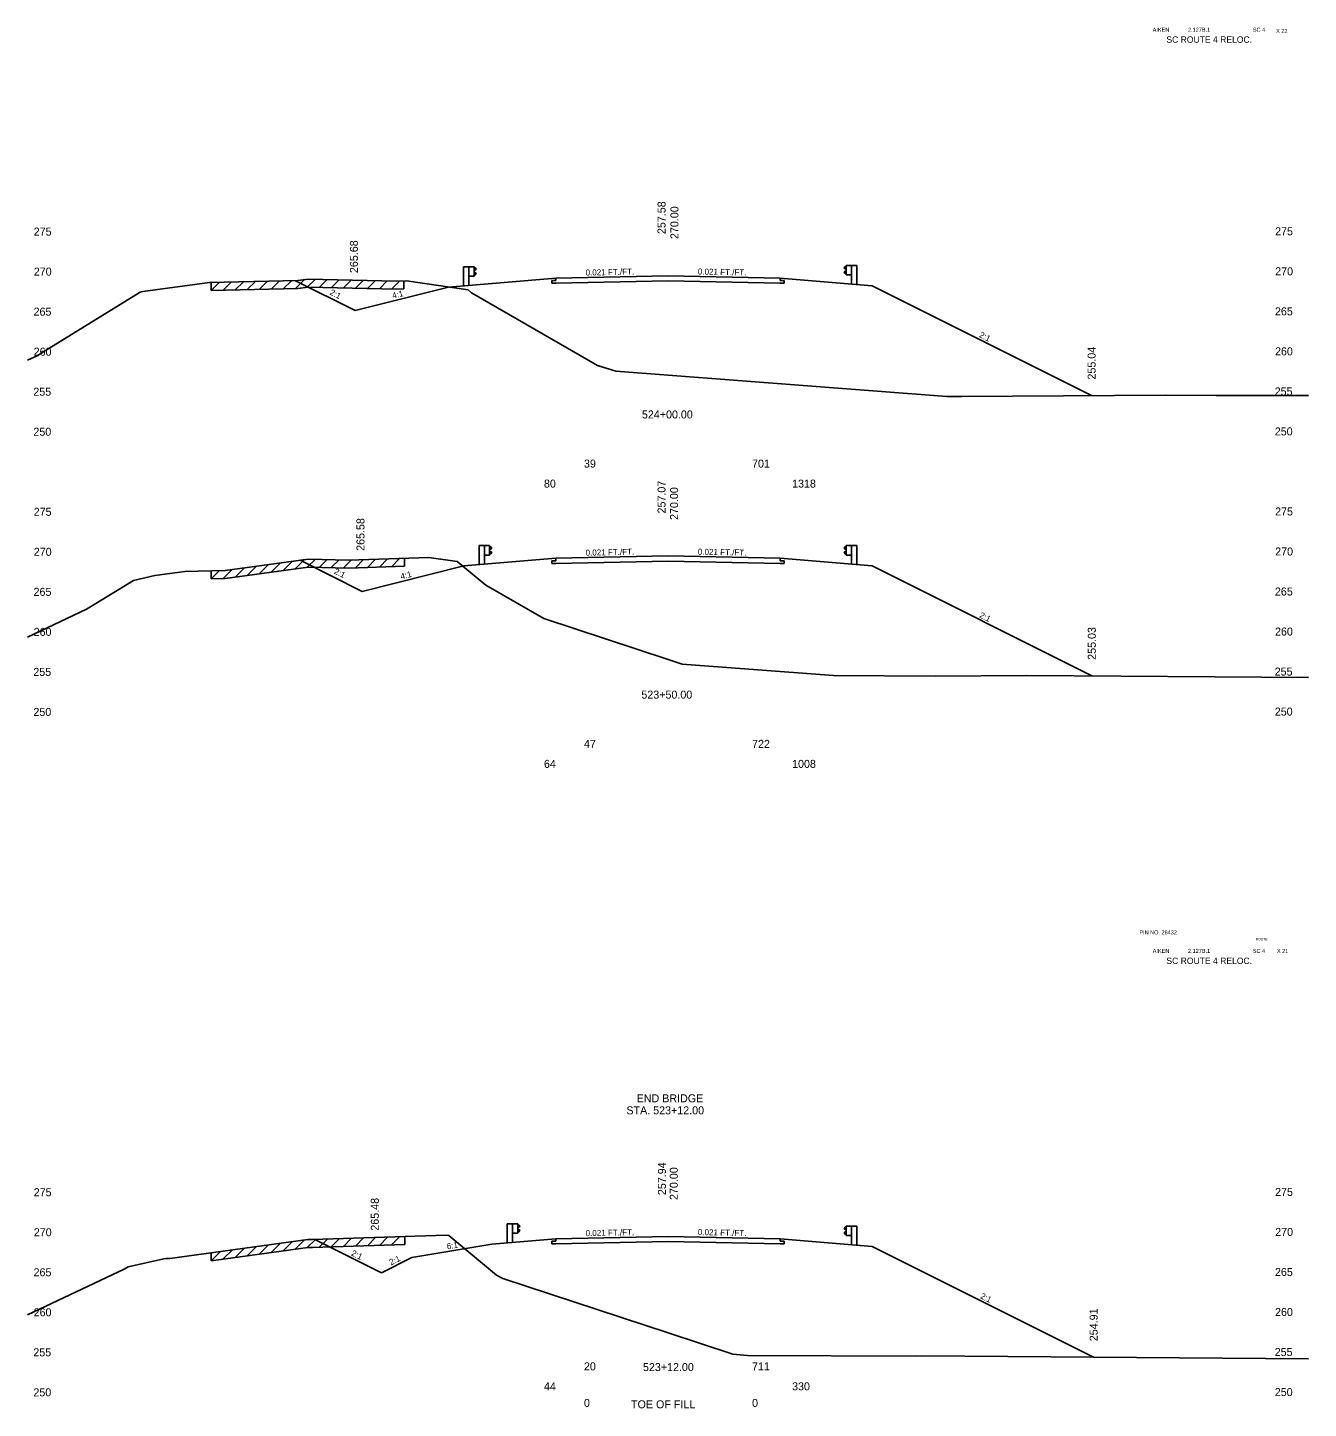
# Model space of a CAD drawing. Extents: x 2967 to 4323, y -3677 to -817.
# Drawn here: x 3188.8 to 3348.8, y -1336.3 to -1163.8 of the extents above; entities that cross this region are included whole.
import ezdxf

# ---------------------------------------------------------------- set-up
doc = ezdxf.new("R2010")
doc.units = 0
for name, color, linetype in [('Level 1', 7, 'Continuous'), ('Level 10', 7, 'Continuous'), ('Level 11', 7, 'Continuous'), ('Level 12', 7, 'Continuous'), ('Level 20', 7, 'Continuous'), ('Level 24', 7, 'Continuous'), ('Level 3', 7, 'Continuous'), ('Level 32', 7, 'Continuous'), ('Level 33', 7, 'Continuous'), ('Level 59', 7, 'Continuous'), ('Level 6', 7, 'Continuous'), ('Level 60', 7, 'Continuous'), ('Level 61', 7, 'Continuous'), ('Level 7', 7, 'Continuous')]:
    doc.layers.add(name, color=color, linetype=linetype)

msp = doc.modelspace()

# ---------------------------------------------------------------- linework, layer by layer
at = {"layer": 'Level 11'}
for p, q in [((3254.76, -1195.13), (3254.76, -1195.43)), ((3282.76, -1195.43), (3282.76, -1195.13)), ((3254.76, -1195.43), (3254.26, -1195.44)), ((3254.26, -1195.44), (3254.26, -1195.78)), ((3254.26, -1195.78), (3254.76, -1195.77)), ((3283.26, -1195.44), (3282.76, -1195.43)), ((3282.76, -1195.77), (3283.26, -1195.78)), ((3283.26, -1195.78), (3283.26, -1195.44)), ((3254.76, -1230.43), (3254.26, -1230.44)), ((3254.26, -1230.44), (3254.26, -1230.78)), ((3254.26, -1230.78), (3254.76, -1230.77)), ((3254.76, -1230.13), (3254.76, -1230.43)), ((3282.76, -1230.43), (3282.76, -1230.13)), ((3283.26, -1230.44), (3282.76, -1230.43)), ((3282.76, -1230.77), (3283.26, -1230.78)), ((3283.26, -1230.78), (3283.26, -1230.44)), ((3254.76, -1315.43), (3254.26, -1315.44)), ((3254.76, -1315.43), (3254.26, -1315.44)), ((3254.26, -1315.44), (3254.26, -1315.78)), ((3254.26, -1315.44), (3254.26, -1315.78)), ((3254.26, -1315.78), (3254.76, -1315.77)), ((3254.26, -1315.78), (3254.76, -1315.77)), ((3254.76, -1315.13), (3254.76, -1315.43)), ((3254.76, -1315.13), (3254.76, -1315.43)), ((3282.76, -1315.43), (3282.76, -1315.13)), ((3282.76, -1315.43), (3282.76, -1315.13)), ((3283.26, -1315.44), (3282.76, -1315.43)), ((3283.26, -1315.44), (3282.76, -1315.43)), ((3282.76, -1315.77), (3283.26, -1315.78)), ((3282.76, -1315.77), (3283.26, -1315.78)), ((3283.26, -1315.78), (3283.26, -1315.44)), ((3283.26, -1315.78), (3283.26, -1315.44))]:
    msp.add_line(p, q, dxfattribs=at)
at = {"layer": 'Level 12'}
for p, q in [((3268.76, -1195.48), (3254.76, -1195.77)), ((3282.76, -1195.77), (3268.76, -1195.48)), ((3268.76, -1230.48), (3254.76, -1230.77)), ((3282.76, -1230.77), (3268.76, -1230.48)), ((3291.03, -1313.62), (3290.76, -1313.82)), ((3290.76, -1313.82), (3290.76, -1313.87)), ((3290.76, -1313.87), (3291.03, -1314.07)), ((3290.76, -1314.39), (3291.03, -1314.19)), ((3291.03, -1314.72), (3291.03, -1313.55)), ((3291.03, -1313.55), (3291.7, -1313.55)), ((3291.7, -1313.55), (3291.7, -1315.88)), ((3291.7, -1313.55), (3292.36, -1313.55)), ((3292.36, -1313.55), (3292.36, -1315.93)), ((3246.76, -1315.8), (3254.76, -1315.13)), ((3254.76, -1315.43), (3254.26, -1315.44)), ((3254.26, -1315.44), (3254.26, -1315.78)), ((3254.26, -1315.78), (3254.76, -1315.77)), ((3254.76, -1315.13), (3268.76, -1314.84)), ((3254.76, -1315.13), (3268.76, -1314.84)), ((3254.76, -1315.13), (3268.76, -1314.84)), ((3254.76, -1315.13), (3254.76, -1315.43)), ((3268.76, -1315.48), (3254.76, -1315.77)), ((3268.76, -1315.48), (3254.76, -1315.77)), ((3268.76, -1315.48), (3254.76, -1315.77)), ((3268.76, -1314.84), (3282.76, -1315.13)), ((3268.76, -1314.84), (3282.76, -1315.13)), ((3268.76, -1314.84), (3282.76, -1315.13)), ((3282.76, -1315.77), (3268.76, -1315.48)), ((3282.76, -1315.77), (3268.76, -1315.48)), ((3282.76, -1315.77), (3268.76, -1315.48)), ((3282.76, -1315.13), (3290.76, -1315.8)), ((3282.76, -1315.43), (3282.76, -1315.13)), ((3283.26, -1315.44), (3282.76, -1315.43)), ((3282.76, -1315.77), (3283.26, -1315.78)), ((3283.26, -1315.78), (3283.26, -1315.44)), ((3290.76, -1314.44), (3290.76, -1314.39)), ((3291.03, -1314.64), (3290.76, -1314.44)), ((3290.76, -1315.8), (3294.26, -1316.09)), ((3291.03, -1314.72), (3291.7, -1314.72)), ((3294.26, -1316.09), (3321.93, -1329.93))]:
    msp.add_line(p, q, dxfattribs=at)
at = {"layer": 'Level 24'}
for p, q in [((3291.03, -1194.72), (3291.03, -1193.55)), ((3291.03, -1193.55), (3291.7, -1193.55)), ((3291.7, -1193.55), (3291.7, -1195.88)), ((3291.7, -1193.55), (3292.36, -1193.55)), ((3292.36, -1193.55), (3292.36, -1195.93)), ((3243.21, -1193.71), (3243.21, -1196.1)), ((3243.21, -1193.71), (3243.88, -1193.71)), ((3244.54, -1193.71), (3243.88, -1193.71)), ((3243.88, -1193.71), (3243.88, -1196.04)), ((3244.54, -1194.88), (3243.88, -1194.88)), ((3244.54, -1194.88), (3244.54, -1193.71)), ((3244.54, -1193.78), (3244.81, -1193.98)), ((3244.81, -1194.03), (3244.54, -1194.23)), ((3244.81, -1194.56), (3244.54, -1194.36)), ((3244.54, -1194.81), (3244.81, -1194.61)), ((3244.81, -1193.98), (3244.81, -1194.03)), ((3244.81, -1194.61), (3244.81, -1194.56)), ((3291.03, -1193.62), (3290.76, -1193.82)), ((3290.76, -1193.82), (3290.76, -1193.87)), ((3290.76, -1193.87), (3291.03, -1194.07)), ((3290.76, -1194.39), (3291.03, -1194.19)), ((3290.76, -1194.44), (3290.76, -1194.39)), ((3291.03, -1194.64), (3290.76, -1194.44)), ((3291.03, -1194.72), (3291.7, -1194.72)), ((3245.15, -1228.55), (3245.15, -1230.93)), ((3245.15, -1228.55), (3245.82, -1228.55)), ((3246.48, -1228.55), (3245.82, -1228.55)), ((3245.82, -1228.55), (3245.82, -1230.88)), ((3246.48, -1229.72), (3245.82, -1229.72)), ((3246.48, -1229.72), (3246.48, -1228.55)), ((3246.48, -1228.62), (3246.76, -1228.82)), ((3246.76, -1228.87), (3246.48, -1229.07)), ((3246.76, -1229.39), (3246.48, -1229.19)), ((3246.48, -1229.64), (3246.76, -1229.44)), ((3246.76, -1228.82), (3246.76, -1228.87)), ((3246.76, -1229.44), (3246.76, -1229.39)), ((3291.03, -1228.62), (3290.76, -1228.82)), ((3290.76, -1228.82), (3290.76, -1228.87)), ((3290.76, -1228.87), (3291.03, -1229.07)), ((3290.76, -1229.39), (3291.03, -1229.19)), ((3290.76, -1229.44), (3290.76, -1229.39)), ((3291.03, -1229.64), (3290.76, -1229.44)), ((3291.03, -1229.72), (3291.03, -1228.55)), ((3291.03, -1228.55), (3291.7, -1228.55)), ((3291.03, -1229.72), (3291.7, -1229.72)), ((3291.7, -1228.55), (3291.7, -1230.88)), ((3291.7, -1228.55), (3292.36, -1228.55)), ((3292.36, -1228.55), (3292.36, -1230.93)), ((3248.66, -1313.26), (3248.66, -1315.64)), ((3248.66, -1313.26), (3249.32, -1313.26)), ((3249.99, -1313.26), (3249.32, -1313.26)), ((3249.32, -1313.26), (3249.32, -1315.59)), ((3249.99, -1314.42), (3249.99, -1313.26)), ((3249.99, -1313.33), (3250.26, -1313.53)), ((3250.26, -1313.58), (3249.99, -1313.78)), ((3250.26, -1314.1), (3249.99, -1313.9)), ((3249.99, -1314.35), (3250.26, -1314.15)), ((3250.26, -1313.53), (3250.26, -1313.58)), ((3250.26, -1314.15), (3250.26, -1314.1)), ((3291.03, -1313.62), (3290.76, -1313.82)), ((3291.03, -1313.62), (3290.76, -1313.82)), ((3290.76, -1313.82), (3290.76, -1313.87)), ((3290.76, -1313.82), (3290.76, -1313.87)), ((3290.76, -1313.87), (3291.03, -1314.07)), ((3290.76, -1313.87), (3291.03, -1314.07)), ((3290.76, -1314.39), (3291.03, -1314.19)), ((3290.76, -1314.39), (3291.03, -1314.19)), ((3291.03, -1314.72), (3291.03, -1313.55)), ((3291.03, -1313.55), (3291.7, -1313.55)), ((3291.03, -1314.72), (3291.03, -1313.55)), ((3291.03, -1313.55), (3291.7, -1313.55)), ((3291.7, -1313.55), (3291.7, -1315.88)), ((3291.7, -1313.55), (3292.36, -1313.55)), ((3291.7, -1313.55), (3291.7, -1315.88)), ((3291.7, -1313.55), (3292.36, -1313.55)), ((3292.36, -1313.55), (3292.36, -1315.93)), ((3292.36, -1313.55), (3292.36, -1315.93)), ((3249.99, -1314.42), (3249.32, -1314.42)), ((3290.76, -1314.44), (3290.76, -1314.39)), ((3290.76, -1314.44), (3290.76, -1314.39)), ((3291.03, -1314.64), (3290.76, -1314.44)), ((3291.03, -1314.64), (3290.76, -1314.44)), ((3291.03, -1314.72), (3291.7, -1314.72)), ((3291.03, -1314.72), (3291.7, -1314.72))]:
    msp.add_line(p, q, dxfattribs=at)
at = {"layer": 'Level 59'}
for p, q in [((3254.76, -1195.13), (3268.76, -1194.84)), ((3268.76, -1194.84), (3282.76, -1195.13)), ((3254.76, -1230.13), (3268.76, -1229.84)), ((3268.76, -1229.84), (3282.76, -1230.13)), ((3254.76, -1315.13), (3268.76, -1314.84)), ((3254.76, -1315.13), (3268.76, -1314.84)), ((3268.76, -1314.84), (3282.76, -1315.13)), ((3268.76, -1314.84), (3282.76, -1315.13))]:
    msp.add_line(p, q, dxfattribs=at)
at = {"layer": 'Level 6'}
for p, q in [((3241.32, -1196.25), (3254.76, -1195.13)), ((3282.76, -1195.13), (3290.76, -1195.8)), ((3241.32, -1196.25), (3229.67, -1199.17)), ((3290.76, -1195.8), (3294.26, -1196.09)), ((3243.26, -1231.09), (3230.57, -1234.26)), ((3243.26, -1231.09), (3254.76, -1230.13)), ((3282.76, -1230.13), (3290.76, -1230.8)), ((3290.76, -1230.8), (3294.26, -1231.09)), ((3246.76, -1315.8), (3254.76, -1315.13)), ((3246.76, -1315.8), (3254.76, -1315.13)), ((3282.76, -1315.13), (3290.76, -1315.8)), ((3282.76, -1315.13), (3290.76, -1315.8)), ((3290.76, -1315.8), (3294.26, -1316.09)), ((3290.76, -1315.8), (3294.26, -1316.09))]:
    msp.add_line(p, q, dxfattribs=at)
at = {"layer": 'Level 60'}
for p, q in [((3222.52, -1195.44), (3223.81, -1195.27)), ((3223.81, -1195.27), (3234.84, -1195.51)), ((3190.86, -1204.27), (3202.82, -1196.9)), ((3202.82, -1196.9), (3203.17, -1196.82)), ((3203.17, -1196.82), (3211.46, -1195.66)), ((3211.46, -1195.66), (3222.52, -1195.44)), ((3234.84, -1195.51), (3236.08, -1195.47)), ((3236.08, -1195.47), (3243.78, -1196.58)), ((3243.78, -1196.58), (3244.23, -1196.95)), ((3244.23, -1196.95), (3259.96, -1206.03)), ((3188.76, -1205.38), (3189.94, -1204.82)), ((3189.94, -1204.82), (3190.86, -1204.27)), ((3259.96, -1206.03), (3262.23, -1206.77)), ((3262.23, -1206.77), (3268.76, -1207.27)), ((3268.76, -1207.27), (3303.6, -1209.91)), ((3303.6, -1209.91), (3305.42, -1209.92)), ((3305.42, -1209.92), (3330.89, -1209.74)), ((3330.89, -1209.74), (3337.23, -1209.78)), ((3337.23, -1209.78), (3348.76, -1209.78)), ((3213.43, -1231.66), (3223.79, -1230.24)), ((3223.79, -1230.24), (3228.89, -1230.35)), ((3228.89, -1230.35), (3238.89, -1230.03)), ((3238.89, -1230.03), (3242.42, -1230.54)), ((3242.42, -1230.54), (3245.99, -1233.49)), ((3196.53, -1236.25), (3201.98, -1232.89)), ((3201.98, -1232.89), (3204.64, -1232.28)), ((3204.64, -1232.28), (3208.41, -1231.76)), ((3208.41, -1231.76), (3213.43, -1231.66)), ((3245.99, -1233.49), (3253.23, -1237.67)), ((3188.76, -1239.97), (3196.11, -1236.5)), ((3196.11, -1236.5), (3196.53, -1236.25)), ((3253.23, -1237.67), (3268.76, -1242.77)), ((3268.76, -1242.77), (3270.54, -1243.36)), ((3270.54, -1243.36), (3289.44, -1244.79)), ((3289.44, -1244.79), (3302.12, -1244.84)), ((3302.12, -1244.84), (3313.6, -1244.76)), ((3313.6, -1244.76), (3348.76, -1245.01)), ((3206.51, -1317.58), (3223.77, -1315.21)), ((3223.77, -1315.21), (3224.36, -1315.23)), ((3224.36, -1315.23), (3241.03, -1314.69)), ((3241.03, -1314.69), (3241.39, -1314.74)), ((3241.39, -1314.74), (3247.33, -1319.66)), ((3201.34, -1318.65), (3205.76, -1317.63)), ((3205.76, -1317.63), (3206.08, -1317.58)), ((3206.08, -1317.58), (3206.51, -1317.58)), ((3188.76, -1324.65), (3200.84, -1318.95)), ((3200.84, -1318.95), (3201.34, -1318.65)), ((3247.33, -1319.66), (3248.12, -1320.11)), ((3248.12, -1320.11), (3268.76, -1326.9)), ((3268.76, -1326.9), (3276.85, -1329.56)), ((3276.85, -1329.56), (3278.68, -1329.7)), ((3278.68, -1329.7), (3299.62, -1329.78)), ((3299.62, -1329.78), (3300.46, -1329.77)), ((3300.46, -1329.77), (3348.76, -1330.12))]:
    msp.add_line(p, q, dxfattribs=at)
at = {"layer": 'Level 61'}
for p, q in [((3224.7, -1195.29), (3223.7, -1196.28)), ((3212.72, -1195.64), (3211.7, -1196.66)), ((3211.7, -1195.66), (3211.7, -1196.66)), ((3211.7, -1196.66), (3222.52, -1196.44)), ((3214.22, -1195.61), (3213.2, -1196.63)), ((3215.72, -1195.58), (3214.7, -1196.6)), ((3217.22, -1195.55), (3216.2, -1196.57)), ((3218.72, -1195.52), (3217.7, -1196.54)), ((3220.22, -1195.49), (3219.2, -1196.51)), ((3221.72, -1195.46), (3220.7, -1196.48)), ((3223.32, -1195.34), (3222.2, -1196.45)), ((3222.52, -1196.44), (3223.81, -1196.27)), ((3223.81, -1196.27), (3234.84, -1196.51)), ((3226.18, -1195.32), (3225.2, -1196.3)), ((3227.68, -1195.35), (3226.7, -1196.33)), ((3229.18, -1195.39), (3228.2, -1196.36)), ((3230.68, -1195.42), (3229.7, -1196.4)), ((3232.18, -1195.45), (3231.2, -1196.43)), ((3233.68, -1195.48), (3232.7, -1196.46)), ((3235.2, -1195.5), (3234.2, -1196.5)), ((3234.84, -1196.51), (3235.77, -1196.48)), ((3235.77, -1196.48), (3235.77, -1195.48)), ((3213.43, -1232.66), (3223.79, -1231.24)), ((3215.86, -1231.32), (3214.7, -1232.48)), ((3217.36, -1231.12), (3216.2, -1232.28)), ((3218.86, -1230.91), (3217.7, -1232.07)), ((3220.36, -1230.71), (3219.2, -1231.87)), ((3221.86, -1230.5), (3220.7, -1231.66)), ((3223.36, -1230.3), (3222.2, -1231.46)), ((3224.69, -1230.26), (3223.7, -1231.25)), ((3223.79, -1231.24), (3228.89, -1231.35)), ((3226.18, -1230.29), (3225.2, -1231.27)), ((3227.68, -1230.32), (3226.7, -1231.3)), ((3229.2, -1230.34), (3228.2, -1231.33)), ((3228.89, -1231.35), (3235.83, -1231.13)), ((3230.73, -1230.29), (3229.7, -1231.32)), ((3232.23, -1230.24), (3231.2, -1231.27)), ((3233.73, -1230.19), (3232.7, -1231.23)), ((3235.23, -1230.14), (3234.2, -1231.18)), ((3235.83, -1231.13), (3235.83, -1230.13)), ((3212.72, -1231.67), (3211.7, -1232.69)), ((3211.7, -1231.69), (3211.7, -1232.69)), ((3211.7, -1232.69), (3213.43, -1232.66)), ((3214.33, -1231.53), (3213.2, -1232.66)), ((3218.86, -1315.89), (3217.7, -1317.05)), ((3220.36, -1315.68), (3219.2, -1316.84)), ((3221.86, -1315.48), (3220.7, -1316.64)), ((3223.36, -1315.27), (3222.2, -1316.43)), ((3224.71, -1315.22), (3223.7, -1316.23)), ((3224.36, -1316.23), (3235.88, -1315.86)), ((3226.23, -1315.17), (3225.2, -1316.2)), ((3227.73, -1315.12), (3226.7, -1316.15)), ((3229.23, -1315.07), (3228.2, -1316.1)), ((3230.73, -1315.02), (3229.7, -1316.06)), ((3232.23, -1314.97), (3231.2, -1316.01)), ((3233.73, -1314.93), (3232.7, -1315.96)), ((3235.23, -1314.88), (3234.2, -1315.91)), ((3235.88, -1315.86), (3235.88, -1314.86)), ((3211.7, -1317.87), (3223.77, -1316.21)), ((3212.86, -1316.71), (3211.7, -1317.87)), ((3211.7, -1316.87), (3211.7, -1317.87)), ((3214.36, -1316.5), (3213.2, -1317.66)), ((3215.86, -1316.3), (3214.7, -1317.46)), ((3217.36, -1316.09), (3216.2, -1317.25)), ((3223.77, -1316.21), (3224.36, -1316.23))]:
    msp.add_line(p, q, dxfattribs=at)
at = {"layer": 'Level 7'}
for p, q in [((3222.23, -1195.45), (3229.67, -1199.17)), ((3294.26, -1196.09), (3321.68, -1209.8)), ((3222.79, -1230.37), (3230.57, -1234.26)), ((3294.26, -1231.09), (3321.7, -1244.81)), ((3224.66, -1315.22), (3232.96, -1319.37)), ((3236.76, -1317.47), (3246.76, -1315.8)), ((3236.76, -1317.47), (3232.96, -1319.37)), ((3294.26, -1316.09), (3321.93, -1329.93)), ((3294.26, -1316.09), (3321.93, -1329.93))]:
    msp.add_line(p, q, dxfattribs=at)

# ---------------------------------------------------------------- texts
at = {"layer": 'Level 1'}
for s, p in [('39', (3258.26, -1218.8)), ('701', (3279.26, -1218.8)), ('80', (3253.26, -1221.3)), ('1318', (3284.26, -1221.3)), ('47', (3258.26, -1253.81)), ('722', (3279.26, -1253.81)), ('64', (3253.26, -1256.31)), ('1008', (3284.26, -1256.31)), ('STA. 523+12.00', (3263.56, -1299.59)), ('END BRIDGE', (3264.84, -1298.09)), ('20', (3258.26, -1331.57)), ('711', (3279.26, -1331.57)), ('44', (3253.26, -1334.07)), ('330', (3284.26, -1334.07)), ('0', (3258.26, -1336.14)), ('0', (3279.26, -1336.14))]:
    msp.add_text(s, height=1, dxfattribs=at).set_placement(p)
at = {"layer": 'Level 10'}
for s, p in [('257.58', (3268.45, -1189.63)), ('257.07', (3268.45, -1224.53)), ('257.94', (3268.5, -1309.68))]:
    msp.add_text(s, height=1, rotation=90, dxfattribs=at).set_placement(p)
for s, p in [('524+00.00', (3265.5, -1212.66)), ('523+50.00', (3265.43, -1247.66)), ('523+12.00', (3265.63, -1331.66)), ('TOE OF FILL', (3264.14, -1336.31))]:
    msp.add_text(s, height=1, dxfattribs=at).set_placement(p)
at = {"layer": 'Level 20'}
for s, height, p in [('AIKEN', 0.5, (3329.31, -1164.35)), (' 2.127B.1', 0.5, (3333.53, -1164.35)), ('SC 4', 0.5, (3341.82, -1164.35)), ('X 22', 0.5, (3344.73, -1164.51)), ('SC ROUTE 4 RELOC.', 0.8, (3331.02, -1165.73)), ('PIN NO. 26432', 0.5, (3327.65, -1277.11)), ('ROUTE', 0.3, (3342.19, -1277.85)), ('AIKEN', 0.5, (3329.31, -1279.42)), (' 2.127B.1', 0.5, (3333.53, -1279.42)), ('SC 4', 0.5, (3341.82, -1279.42)), ('X 21', 0.5, (3344.83, -1279.43)), ('SC ROUTE 4 RELOC.', 0.8, (3331.02, -1280.81))]:
    msp.add_text(s, height=height, dxfattribs=at).set_placement(p)
at = {"layer": 'Level 3'}
for s, p in [(' 275', (3189.15, -1189.82)), (' 275', (3344.23, -1189.78)), (' 270', (3189.16, -1194.82)), (' 270', (3344.24, -1194.78)), (' 265', (3189.13, -1199.82)), (' 265', (3344.21, -1199.78)), (' 260', (3189.14, -1204.82)), (' 260', (3344.22, -1204.78)), (' 255', (3189.1, -1209.82)), (' 255', (3344.18, -1209.78)), (' 250', (3189.11, -1214.82)), (' 250', (3344.19, -1214.78)), (' 275', (3189.15, -1224.82)), (' 275', (3344.23, -1224.78)), (' 270', (3189.16, -1229.82)), (' 270', (3344.24, -1229.78)), (' 265', (3189.13, -1234.82)), (' 265', (3344.21, -1234.78)), (' 260', (3189.14, -1239.82)), (' 260', (3344.22, -1239.78)), (' 255', (3189.1, -1244.82)), (' 255', (3344.18, -1244.78)), (' 250', (3344.19, -1249.78)), (' 250', (3189.11, -1249.82)), (' 275', (3189.15, -1309.82)), (' 275', (3344.23, -1309.78)), (' 270', (3189.16, -1314.82)), (' 270', (3344.24, -1314.78)), (' 265', (3189.13, -1319.82)), (' 265', (3344.21, -1319.78)), (' 260', (3189.14, -1324.82)), (' 260', (3344.22, -1324.78)), (' 255', (3189.1, -1329.82)), (' 255', (3344.18, -1329.78)), (' 250', (3189.11, -1334.82)), (' 250', (3344.19, -1334.78))]:
    msp.add_text(s, height=1, dxfattribs=at).set_placement(p)
at = {"layer": 'Level 32'}
for s, rotation, p in [('0.021 FT./FT.', 1.1916, (3258.47, -1194.81)), ('0.021 FT./FT.', 358.8084, (3272.48, -1194.67)), ('2:1', 333.435, (3226.43, -1197.15)), ('4:1', 14.0362, (3234.4, -1197.71)), ('2:1', 333.435, (3307.57, -1202.47)), ('0.021 FT./FT.', 1.1916, (3258.47, -1229.81)), ('0.021 FT./FT.', 358.8084, (3272.48, -1229.67)), ('2:1', 333.435, (3226.97, -1232)), ('4:1', 14.0362, (3235.44, -1232.78)), ('2:1', 333.435, (3307.59, -1237.48)), ('0.021 FT./FT.', 1.1916, (3258.47, -1314.81)), ('0.021 FT./FT.', 1.1916, (3258.47, -1314.81)), ('0.021 FT./FT.', 1.1916, (3258.47, -1314.81)), ('0.021 FT./FT.', 358.8084, (3272.48, -1314.67)), ('0.021 FT./FT.', 358.8084, (3272.48, -1314.67)), ('6:1', 9.4623, (3241.19, -1316.47)), ('2:1', 333.435, (3229.11, -1317.17)), ('2:1', 26.5651, (3234.16, -1318.46)), ('2:1', 333.435, (3307.7, -1322.53)), ('2:1', 333.435, (3307.7, -1322.53)), ('2:1', 333.435, (3307.7, -1322.53))]:
    msp.add_text(s, height=0.75, rotation=rotation, dxfattribs=at).set_placement(p)
at = {"layer": 'Level 33'}
for s, p in [('265.68', (3230.02, -1194.5)), ('255.04', (3322.18, -1207.8)), ('265.58', (3230.84, -1229.2)), ('255.03', (3322.2, -1242.81)), ('265.48', (3232.63, -1314.12)), ('254.91', (3322.43, -1327.93)), ('254.91', (3322.43, -1327.93)), ('254.91', (3322.43, -1327.93))]:
    msp.add_text(s, height=1, rotation=90, dxfattribs=at).set_placement(p)
at = {"layer": 'Level 59'}
for p in [(3270.06, -1190.62), (3270.02, -1225.71), (3269.98, -1310.66)]:
    msp.add_text(' 270.00', height=1, rotation=90, dxfattribs=at).set_placement(p)

doc.saveas('drawing.dxf')
